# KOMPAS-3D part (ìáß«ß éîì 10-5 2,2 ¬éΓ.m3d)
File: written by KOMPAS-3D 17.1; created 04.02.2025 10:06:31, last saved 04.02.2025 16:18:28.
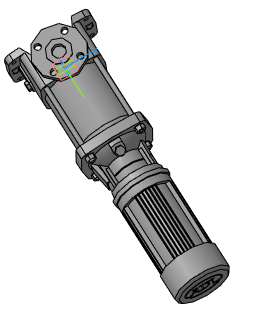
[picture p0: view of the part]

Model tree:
1. Операция без истории:2  (labels: Насос ВМН 10-5 2,2 кВт)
